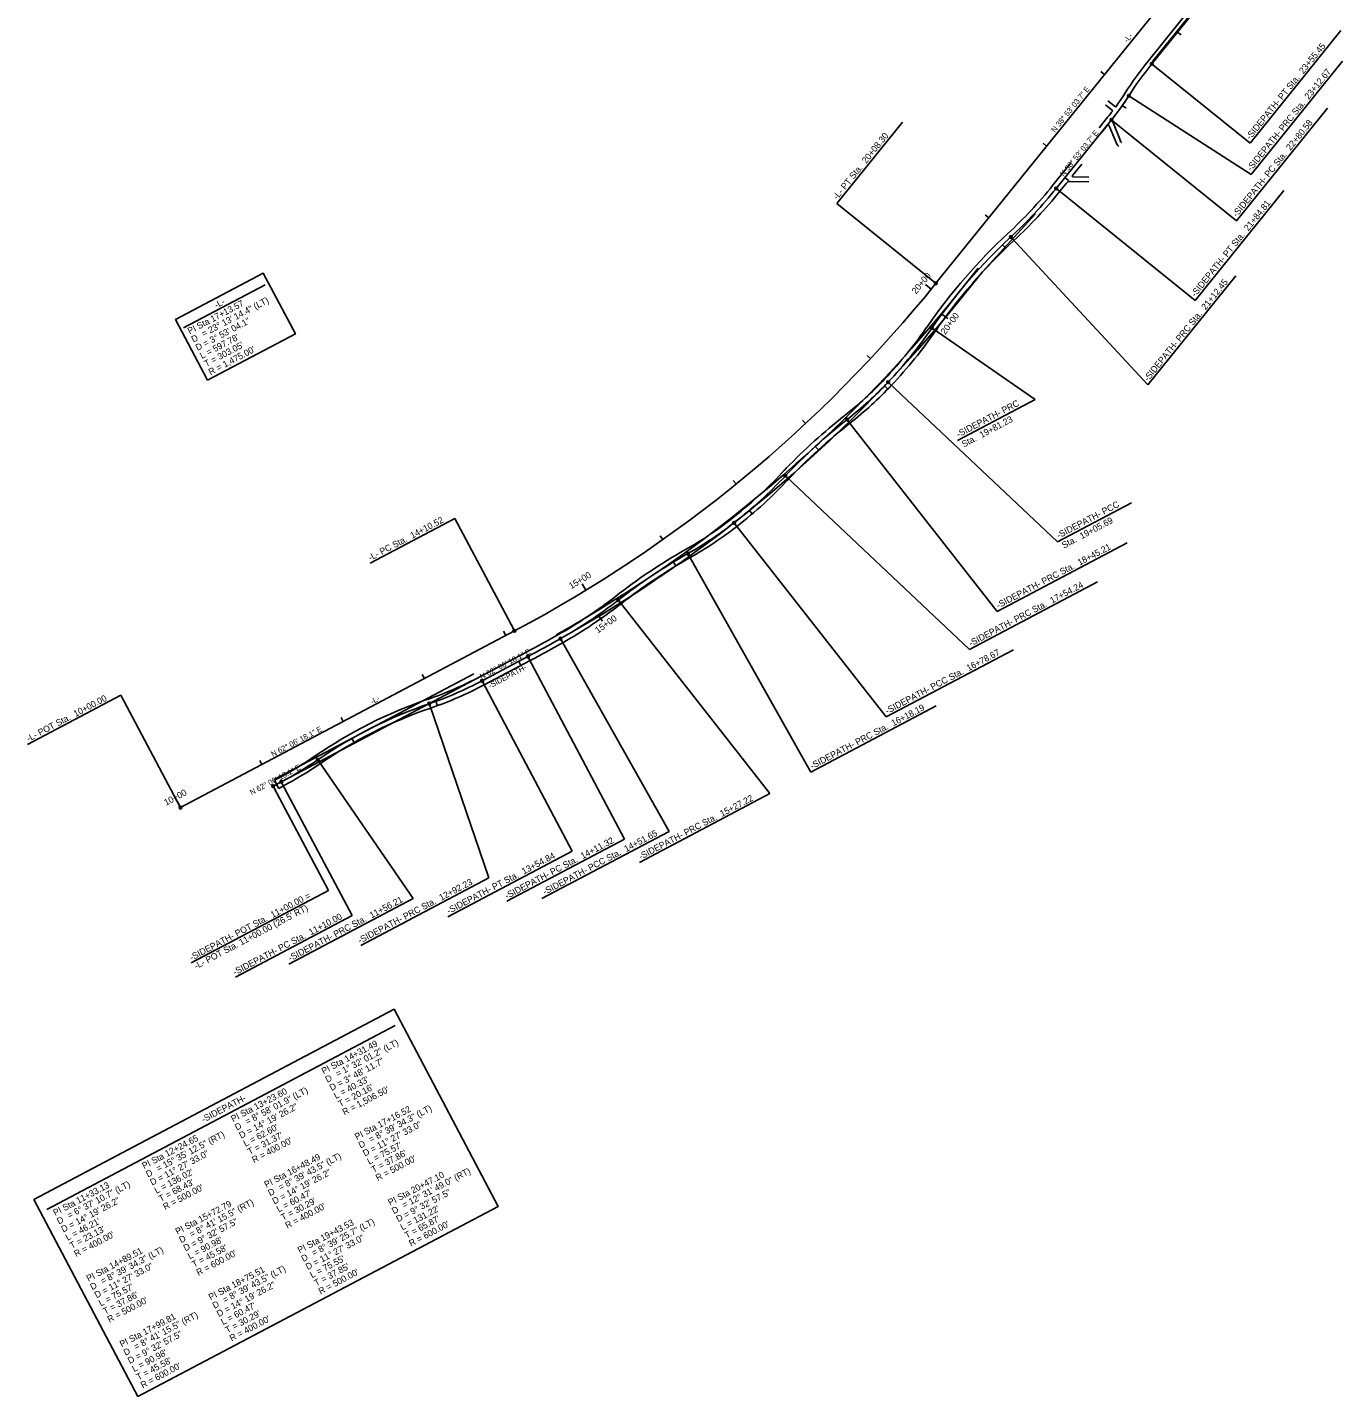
# Model space of a CAD drawing. Extents: x 1487048 to 1489168, y 497704 to 500108.
# Drawn here: x 1487586 to 1489015, y 497704 to 499192 of the extents above; entities that cross this region are included whole.
import ezdxf

# ---------------------------------------------------------------- set-up
doc = ezdxf.new("R2010")
doc.units = 0
for name, color, linetype in [('Prop Conc 4in Sidewalk', 7, 'Continuous'), ('Prop Grid Mask', 7, 'Continuous'), ('Prop Horizontal Alignment', 7, 'Continuous'), ('Prop Horizontal Alignment Curve and Spiral Data', 7, 'Continuous'), ('Prop Horizontal Alignment Direction Label', 7, 'Continuous'), ('Prop Horizontal Alignment Station Label', 7, 'Continuous'), ('Prop Horizontal Alignment Tick Label', 7, 'Continuous'), ('Prop Horizontal Alignment Tick Large', 7, 'Continuous'), ('Prop Horizontal Alignment Tick Small', 7, 'Continuous'), ('Scratch_Level_5', 7, 'Continuous')]:
    doc.layers.add(name, color=color, linetype=linetype)

msp = doc.modelspace()

# ---------------------------------------------------------------- linework, layer by layer
at = {"layer": 'Prop Conc 4in Sidewalk'}
for p, q in [((1488803.9, 499155.4), (1488854.2, 499217.8)), ((1488807.8, 499152.3), (1488861.1, 499218.3)), ((1488757.6, 499107.7), (1488765.4, 499101.4)), ((1488759.9, 499112.3), (1488768.4, 499105.5)), ((1488750.6, 499083), (1488760.1, 499094.7)), ((1488773.6, 499068.7), (1488765.4, 499089.3)), ((1488753.3, 499078.3), (1488759.1, 499085.5)), ((1488768.9, 499066.8), (1488761.6, 499085.1)), ((1488700, 499020.2), (1488720, 499045)), ((1488721.6, 499031.1), (1488731.6, 499043.4)), ((1488739.5, 499029.1), (1488722.4, 499029.5)), ((1488707.8, 499013.9), (1488714.9, 499022.7)), ((1488739.4, 499024.1), (1488718.9, 499024.6)), ((1488077.5, 498486.3), (1488127.4, 498512.7)), ((1488082.2, 498477.5), (1488132.1, 498503.9)), ((1487854.4, 498373.9), (1487859.5, 498376.6)), ((1487859.1, 498365), (1487854.4, 498373.9)), ((1487859.1, 498365), (1487864.2, 498367.7))]:
    msp.add_line(p, q, dxfattribs=at)
for centre, radius, start, end in [((1489119.1, 498901.2), 405, 141.1156, 147.2437), ((1489119.1, 498901.2), 400, 141.1156, 147.2437), ((1488530.5, 499279.9), 300, 321.7531, 327.2437), ((1488530.5, 499279.9), 295, 323.7475, 327.2437), ((1488530.5, 499279.9), 295, 321.1156, 322.7757), ((1488760.3, 499084.6), 1.5, 22.2994, 142.2924), ((1488770, 499091.1), 5, 139.2751, 201.6281), ((1488778.2, 499070.5), 10, 201.6281, 231.1156), ((1488778.2, 499070.5), 5, 201.6281, 231.1156), ((1488722.4, 499030.5), 1, 141.1156, 268.6989), ((1488314.7, 499330.9), 495, 312.8235, 321.1156), ((1488314.7, 499330.9), 505, 312.8235, 321.1156), ((1488718.8, 499019.6), 5, 88.6989, 141.1156), ((1489062.4, 498524.1), 605, 132.8235, 145.3537), ((1489062.4, 498524.1), 595, 132.8235, 145.3537), ((1488157.4, 499149.5), 495, 316.6966, 325.3537), ((1488157.4, 499149.5), 505, 316.6966, 325.3537), ((1488230.2, 499080.9), 395, 308.0345, 316.6966), ((1488230.2, 499080.9), 405, 308.0345, 316.6966), ((1488846.3, 498293.2), 605, 128.0345, 136.036), ((1488846.3, 498293.2), 595, 128.0345, 136.7222), ((1488045.5, 499047.3), 495, 308.0626, 316.7222), ((1488045.5, 499047.3), 505, 308.0626, 316.7222), ((1488846.3, 498293.2), 605, 136.5115, 136.7222), ((1488846.3, 498293.2), 605, 136.036, 136.5115), ((1488107.1, 498968.6), 395, 299.4005, 308.0626), ((1488107.1, 498968.6), 405, 299.4005, 308.0626), ((1488598.1, 498097.4), 605, 119.4005, 128.0882), ((1488598.1, 498097.4), 595, 119.4005, 128.0882), ((1487919.5, 498963.2), 495, 299.4286, 308.0882), ((1487919.5, 498963.2), 505, 299.4286, 308.0882), ((1487425, 499839.8), 1501.5, 297.895, 299.4286), ((1487425, 499839.8), 1511.5, 297.895, 299.4286), ((1487892.7, 498835.4), 395, 288.9278, 297.895), ((1487892.7, 498835.4), 405, 288.9278, 297.895), ((1488184.7, 497984.1), 505, 108.9278, 124.5146), ((1488184.7, 497984.1), 495, 108.9278, 124.5146), ((1487674.7, 498725.7), 395, 297.895, 304.5146), ((1487674.7, 498725.7), 405, 297.895, 304.5146)]:
    msp.add_arc(centre, radius, start, end, dxfattribs=at)
at = {"layer": 'Prop Grid Mask'}
for points in [[(1487781.4, 498808.5), (1487877, 498859), (1487842.2, 498924.9), (1487746.6, 498874.4)], [(1487706, 497704), (1488097.5, 497910.7), (1487984.4, 498124.9), (1487592.9, 497918.2)]]:
    msp.add_lwpolyline(points, close=True, dxfattribs=at)
at = {"layer": 'Prop Horizontal Alignment'}
for p, q in [((1488573.1, 498913.9), (1488944.6, 499374.4)), ((1488807.8, 499152.3), (1488912.2, 499281.7)), ((1488703.9, 499017), (1488764, 499091.6)), ((1487752.2, 498344.1), (1488115, 498536.2)), ((1488079.9, 498481.9), (1488129.8, 498508.3)), ((1487853, 498367.5), (1487861.8, 498372.2))]:
    msp.add_line(p, q, dxfattribs=at)
for centre, radius, start, end in [((1489119.1, 498901.2), 400, 141.1156, 147.2437), ((1488530.5, 499279.9), 300, 321.1156, 327.2437), ((1488314.7, 499330.9), 500, 312.8235, 321.1156), ((1489062.4, 498524.1), 600, 132.8235, 145.3537), ((1487425, 499839.8), 1475, 297.895, 321.1156), ((1488157.4, 499149.5), 500, 316.6966, 325.3537), ((1488230.2, 499080.9), 400, 308.0345, 316.6966), ((1488846.3, 498293.2), 600, 128.0345, 136.7222), ((1488045.5, 499047.3), 500, 308.0626, 316.7222), ((1488107.1, 498968.6), 400, 299.4005, 308.0626), ((1488598.1, 498097.4), 600, 119.4005, 128.0882), ((1487919.5, 498963.2), 500, 299.4286, 308.0882), ((1487425, 499839.8), 1506.5, 297.895, 299.4286), ((1487892.7, 498835.4), 400, 288.9278, 297.895), ((1488184.7, 497984.1), 500, 108.9278, 124.5146), ((1487674.7, 498725.7), 400, 297.895, 304.5146)]:
    msp.add_arc(centre, radius, start, end, dxfattribs=at)
at = {"layer": 'Prop Horizontal Alignment Curve and Spiral Data'}
for p, q in [((1487755.3, 498865.4), (1487844.2, 498912.4)), ((1487606.9, 497907.3), (1487985.6, 498107.3))]:
    msp.add_line(p, q, dxfattribs=at)
at = {"layer": 'Prop Horizontal Alignment Station Label'}
for p, q in [((1489013.3, 499188.5), (1488914.6, 499066.1)), ((1488808.9, 499151.3), (1488914.6, 499066.1)), ((1489015.1, 499155.4), (1488915.7, 499032)), ((1488784, 499116.8), (1488915.7, 499032)), ((1488998.6, 499104.3), (1488899.9, 498981.9)), ((1488465.5, 499000.6), (1488536.9, 499089.1)), ((1488765.2, 499090.6), (1488899.9, 498981.9)), ((1488705, 499016.1), (1488854.9, 498895.3)), ((1488951.1, 499014.6), (1488854.9, 498895.3)), ((1488572, 498914.8), (1488465.5, 499000.6)), ((1488655.5, 498963.1), (1488803.5, 498803.4)), ((1488899.2, 498922), (1488803.5, 498803.4)), ((1488570, 498864.4), (1488681.2, 498787.5)), ((1488522.4, 498805.5), (1488705.4, 498633)), ((1488681.2, 498787.5), (1488596.6, 498742.9)), ((1488477.6, 498764.6), (1488639.7, 498557.4)), ((1488410.6, 498703.5), (1488609.7, 498516)), ((1488785.7, 498675.4), (1488705.4, 498633)), ((1487958.4, 498609.8), (1488050.4, 498658.4)), ((1488114.3, 498537.5), (1488050.4, 498658.4)), ((1488354.7, 498652.5), (1488519, 498442.7)), ((1488780.9, 498631.9), (1488639.7, 498557.4)), ((1488304.2, 498618.8), (1488437.3, 498382.8)), ((1488748.6, 498589.4), (1488609.7, 498516)), ((1488228.9, 498568.4), (1488392.8, 498359.3)), ((1488165.9, 498526.4), (1488283.3, 498318.2)), ((1488130.5, 498507), (1488234.9, 498309.8)), ((1488657.3, 498515.7), (1488519, 498442.7)), ((1488080.6, 498480.6), (1488177.8, 498296.9)), ((1487585.8, 498412.6), (1487687.5, 498466.3)), ((1487751.5, 498345.4), (1487687.5, 498466.3)), ((1488023, 498455.6), (1488087.4, 498267.9)), ((1488573.6, 498454.8), (1488437.3, 498382.8)), ((1487902.2, 498394.8), (1488005.1, 498245.2)), ((1487853.7, 498366.1), (1487913, 498254.1)), ((1487862.5, 498370.8), (1487938.8, 498226.7)), ((1488251.1, 498284.4), (1488392.8, 498359.3)), ((1488144.9, 498245.2), (1488283.3, 498318.2)), ((1488107, 498242.3), (1488234.9, 498309.8)), ((1488042.8, 498225.5), (1488177.8, 498296.9)), ((1487948, 498194.3), (1488087.4, 498267.9)), ((1487913, 498254.1), (1487763.9, 498175.4)), ((1487870.1, 498173.8), (1488005.1, 498245.2)), ((1487812, 498159.7), (1487938.8, 498226.7))]:
    msp.add_line(p, q, dxfattribs=at)
for centre in [(1488807.8, 499152.3), (1488782.8, 499117.6), (1488764, 499091.6), (1488703.9, 499017), (1488654.5, 498964.2), (1488573.1, 498913.9), (1488568.8, 498865.2), (1488521.3, 498806.5), (1488476.7, 498765.8), (1488409.5, 498704.6), (1488353.8, 498653.7), (1488303.5, 498620.1), (1488227.9, 498569.6), (1488115, 498536.2), (1488165.2, 498527.7), (1488129.8, 498508.3), (1488079.9, 498481.9), (1488022.5, 498457.1), (1487901.4, 498396.1), (1487861.8, 498372.2), (1487853, 498367.5), (1487752.2, 498344.1)]:
    msp.add_circle(centre, 1.5, dxfattribs=at)
at = {"layer": 'Prop Horizontal Alignment Tick Large'}
for p, q in [((1488567.9, 498907.4), (1488561.7, 498912.5)), ((1488579.7, 498880.5), (1488586.1, 498875.7)), ((1488192.8, 498580.4), (1488188.6, 498587.2)), ((1488206.1, 498553.4), (1488210.7, 498546.9)), ((1487752.2, 498344.1), (1487748.5, 498351.2))]:
    msp.add_line(p, q, dxfattribs=at)
at = {"layer": 'Prop Horizontal Alignment Tick Small'}
for p, q in [((1488835.7, 499186.9), (1488839.6, 499183.8)), ((1488756.2, 499140.9), (1488752.3, 499144.1)), ((1488775.7, 499107.1), (1488779.8, 499104.2)), ((1488693.5, 499063.1), (1488689.6, 499066.2)), ((1488713.4, 499028.9), (1488717.3, 499025.7)), ((1488630.7, 498985.2), (1488626.8, 498988.4)), ((1488645.5, 498955.6), (1488649, 498952)), ((1488502.1, 498832.1), (1488498.5, 498835.5)), ((1488517.4, 498802.4), (1488521, 498798.9)), ((1488431.4, 498761.5), (1488428, 498765.1)), ((1488442.1, 498736.7), (1488445.5, 498733)), ((1488356, 498695.8), (1488352.9, 498699.6)), ((1488370.3, 498667.2), (1488373.5, 498663.4)), ((1488276.4, 498635.3), (1488273.5, 498639.4)), ((1488287.8, 498610.9), (1488290.4, 498606.7)), ((1488105.8, 498531.3), (1488103.4, 498535.7)), ((1488119.8, 498503), (1488122.1, 498498.6)), ((1488017.4, 498484.5), (1488015, 498488.9)), ((1488029.8, 498459.6), (1488031.5, 498454.9)), ((1487929, 498437.7), (1487926.7, 498442.1)), ((1487938.5, 498419.3), (1487940.9, 498414.9)), ((1487840.6, 498390.9), (1487838.3, 498395.3)), ((1487853, 498367.5), (1487855.3, 498363.1))]:
    msp.add_line(p, q, dxfattribs=at)
at = {"layer": 'Scratch_Level_5'}
for p, q in [((1488808.6, 499154.9), (1488923.2, 499297)), ((1488703.9, 499017), (1488764, 499091.6)), ((1488623.8, 498926.5), (1488681.5, 498989.3)), ((1488593, 498897.8), (1488619.2, 498930.3)), ((1488597.6, 498894.1), (1488623.8, 498926.5)), ((1487853, 498367.5), (1488127.4, 498512.7)), ((1487854, 498374.8), (1488070.9, 498489.6))]:
    msp.add_line(p, q, dxfattribs=at)
for radius, start in [(1500.5, 299.3496), (1506.5, 300.128)]:
    msp.add_arc((1487425, 499839.8), radius, start, 321.1156, dxfattribs=at)

# ---------------------------------------------------------------- texts
at = {"layer": 'Prop Horizontal Alignment Curve and Spiral Data'}
for s, p in [('PI Sta 17+13.57', (1487762.1, 498858.4)), ('= 23%%d 13\' 14.4" (LT)', (1487777.4, 498855.5)), ('-L-', (1487791.2, 498886.5)), ('D = 3%%d 53\' 04.1"', (1487770.8, 498840.4)), ('D', (1487766.2, 498849.3)), ("L = 597.78'", (1487775.5, 498831.6)), ("T = 303.05'", (1487780.2, 498822.8)), ("R = 1,475.00'", (1487784.9, 498813.9)), ('PI Sta 14+31.49', (1487907.7, 498054.1)), ('= 1%%d 32\' 01.2" (LT)', (1487923, 498051.2)), ('D = 3%%d 48\' 11.7"', (1487916.4, 498036.1)), ('D', (1487911.8, 498045)), ("L = 40.33'", (1487921.1, 498027.3)), ('-SIDEPATH-', (1487777.2, 498001.6)), ('PI Sta 13+23.60', (1487809.3, 498002.2)), ('= 8%%d 58\' 01.9" (LT)', (1487824.6, 497999.3)), ("T = 20.16'", (1487925.8, 498018.5)), ("R = 1,506.50'", (1487930.4, 498009.6)), ('D = 14%%d 19\' 26.2"', (1487818.1, 497984.2)), ('PI Sta 17+16.52', (1487943.8, 497982.8)), ('= 8%%d 39\' 34.3" (LT)', (1487959.1, 497979.9)), ('D', (1487813.4, 497993.1)), ("L = 62.60'", (1487822.8, 497975.4)), ('D = 11%%d 27\' 33.0"', (1487952.6, 497964.8)), ('PI Sta 12+24.65', (1487712.7, 497951.2)), ('= 15%%d 35\' 12.5" (RT)', (1487728, 497948.3)), ("T = 31.37'", (1487827.4, 497966.5)), ("R = 400.00'", (1487832.1, 497957.7)), ('D = 11%%d 27\' 33.0"', (1487721.4, 497933.2)), ('D', (1487947.9, 497973.6)), ("L = 75.57'", (1487957.3, 497955.9)), ("T = 37.86'", (1487961.9, 497947.1)), ('PI Sta 16+48.49', (1487845.5, 497930.8)), ('= 8%%d 39\' 43.5" (LT)', (1487860.8, 497927.9)), ("R = 500.00'", (1487966.6, 497938.2)), ('D', (1487716.8, 497942)), ("L = 136.02'", (1487726.1, 497924.3)), ("T = 68.43'", (1487730.8, 497915.5)), ('D = 14%%d 19\' 26.2"', (1487854.2, 497912.8)), ('PI Sta 20+47.10', (1487980, 497911.4)), ('= 12%%d 31\' 49.0" (RT)', (1487995.3, 497908.5)), ('PI Sta 11+33.13', (1487616.1, 497900.2)), ('= 6%%d 37\' 10.7" (LT)', (1487631.4, 497897.3)), ("R = 500.00'", (1487735.5, 497906.7)), ('D', (1487849.6, 497921.7)), ("L = 60.47'", (1487858.9, 497904)), ('D = 9%%d 32\' 57.5"', (1487988.8, 497893.4)), ('D = 14%%d 19\' 26.2"', (1487624.8, 497882.2)), ('PI Sta 15+72.79', (1487748.9, 497879.8)), ('= 8%%d 41\' 15.5" (RT)', (1487764.2, 497876.9)), ("T = 30.29'", (1487863.6, 497895.1)), ("R = 400.00'", (1487868.3, 497886.3)), ('D', (1487984.1, 497902.2)), ("L = 131.22'", (1487993.4, 497884.5)), ('D', (1487620.1, 497891)), ("L = 46.21'", (1487629.5, 497873.3)), ('D = 9%%d 32\' 57.5"', (1487757.6, 497861.8)), ('PI Sta 19+43.53', (1487881.7, 497859.5)), ('= 8%%d 39\' 25.7" (LT)', (1487897, 497856.6)), ("T = 65.87'", (1487998.1, 497875.7)), ("T = 23.13'", (1487634.1, 497864.5)), ("R = 400.00'", (1487638.8, 497855.6)), ("R = 600.00'", (1488002.8, 497866.9)), ('= 8%%d 39\' 34.3" (LT)', (1487667.5, 497825.9)), ('D', (1487752.9, 497870.7)), ("L = 90.98'", (1487762.3, 497853)), ("T = 45.58'", (1487766.9, 497844.1)), ('D = 11%%d 27\' 33.0"', (1487890.4, 497841.5)), ('PI Sta 14+89.51', (1487652.2, 497828.8)), ("R = 600.00'", (1487771.6, 497835.3)), ('D', (1487885.7, 497850.3)), ("L = 75.55'", (1487895.1, 497832.6)), ('D = 11%%d 27\' 33.0"', (1487661, 497810.8)), ('PI Sta 18+75.51', (1487785, 497808.4)), ('= 8%%d 39\' 43.5" (LT)', (1487800.3, 497805.5)), ("T = 37.85'", (1487899.7, 497823.8)), ("R = 500.00'", (1487904.4, 497814.9)), ('D', (1487656.3, 497819.6)), ("L = 75.57'", (1487665.6, 497801.9)), ('D = 14%%d 19\' 26.2"', (1487793.8, 497790.4)), ("T = 37.86'", (1487670.3, 497793.1)), ("R = 500.00'", (1487675, 497784.3)), ('D', (1487789.1, 497799.3)), ("L = 60.47'", (1487798.4, 497781.6)), ('PI Sta 17+99.81', (1487688.4, 497757.4)), ('= 8%%d 41\' 15.5" (RT)', (1487703.7, 497754.5)), ("T = 30.29'", (1487803.1, 497772.7)), ("R = 400.00'", (1487807.8, 497763.9)), ('D = 9%%d 32\' 57.5"', (1487697.1, 497739.4)), ('D', (1487692.5, 497748.3)), ("L = 90.98'", (1487701.8, 497730.6)), ("T = 45.58'", (1487706.5, 497721.7)), ("R = 600.00'", (1487711.1, 497712.9))]:
    msp.add_text(s, height=7, rotation=27.8351, dxfattribs=at).set_placement(p)
at = {"layer": 'Prop Horizontal Alignment Direction Label'}
for s, rotation, p in [('-L-', 51.1156, (1488781.3, 499175)), ('N 38%%d 53\' 03.7" E', 51.1156, (1488702.5, 499077.3)), ('N 38%%d 53\' 03.7" E', 51.1156, (1488712.1, 499029.5)), ('N 62%%d 06\' 18.1" E', 27.895, (1488079.4, 498483.3)), ('-SIDEPATH-', 27.895, (1488088.7, 498473.5)), ('-L-', 27.895, (1487960.7, 498456.2)), ('N 62%%d 06\' 18.1" E', 27.895, (1487852.6, 498399)), ('N 62%%d 06\' 18.1" E', 27.895, (1487829.5, 498357.5))]:
    msp.add_text(s, height=6, rotation=rotation, dxfattribs=at).set_placement(p)
at = {"layer": 'Prop Horizontal Alignment Station Label'}
for s, rotation, p in [('-SIDEPATH- PT Sta.  23+55.45', 51.1156, (1488914.7, 499069.3)), ('-SIDEPATH- PRC Sta.  23+12.67', 51.1156, (1488915.7, 499035.3)), ('-SIDEPATH- PC Sta.  22+80.58', 51.1156, (1488900, 498985.2)), ('-L- PT Sta.  20+08.30', 51.1156, (1488465.8, 499004.2)), ('-SIDEPATH- PT Sta.  21+84.81', 51.1156, (1488854.9, 498898.5)), ('-SIDEPATH- PRC Sta.  21+12.45', 51.1156, (1488803.6, 498806.6)), ('-SIDEPATH- PRC', 27.8351, (1488597.7, 498746.2)), ('Sta.  19+81.23', 27.8351, (1488603.4, 498735.4)), ('-SIDEPATH- PCC', 27.8351, (1488706.5, 498636.3)), ('-L- PC Sta.  14+10.52', 27.8351, (1487958.5, 498612.1)), ('Sta.  19+05.69', 27.8351, (1488712.3, 498625.5)), ('-SIDEPATH- PRC Sta.  18+45.21', 27.8351, (1488641, 498560.3)), ('-SIDEPATH- PRC Sta.  17+54.24', 27.8351, (1488611, 498519)), ('-SIDEPATH- PCC Sta.  16+78.67', 27.8351, (1488520.3, 498445.6)), ('-L- POT Sta.  10+00.00', 27.8351, (1487587.1, 498415.5)), ('-SIDEPATH- PRC Sta.  16+18.19', 27.8351, (1488438.6, 498385.7)), ('-SIDEPATH- PRC Sta.  15+27.22', 27.8351, (1488252.3, 498287.3)), ('-SIDEPATH- PCC Sta.  14+51.65', 27.8351, (1488148.2, 498249.1)), ('-SIDEPATH- PC Sta.  14+11.32', 27.8351, (1488106.9, 498244.5)), ('-SIDEPATH- PT Sta.  13+54.84', 27.8351, (1488043.8, 498228.3)), ('-SIDEPATH- PRC Sta.  12+92.23', 27.8351, (1487947.2, 498196.1)), ('-SIDEPATH- POT Sta.  11+00.00 =', 27.8351, (1487764.4, 498177.6)), ("-L- POT Sta. 11+00.00 (26.5' RT)", 27.8351, (1487769.3, 498168.3)), ('-SIDEPATH- PRC Sta.  11+56.21', 27.8351, (1487871.5, 498176.9)), ('-SIDEPATH- PC Sta.  11+10.00', 27.8351, (1487811.5, 498161.7))]:
    msp.add_text(s, height=7, rotation=rotation, dxfattribs=at).set_placement(p)
at = {"layer": 'Prop Horizontal Alignment Tick Label'}
for s, rotation, p in [('20+00', 50.7932, (1488551.6, 498901.7)), ('20+00', 53.5616, (1488583.3, 498857.6)), ('15+00', 31.3709, (1488176.9, 498581.3)), ('15+00', 34.9693, (1488205.7, 498533.2)), ('10+00', 27.895, (1487736.5, 498346))]:
    msp.add_text(s, height=7, rotation=rotation, dxfattribs=at).set_placement(p)

doc.saveas('drawing.dxf')
